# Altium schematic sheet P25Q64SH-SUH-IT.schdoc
size 127 x 101 mm
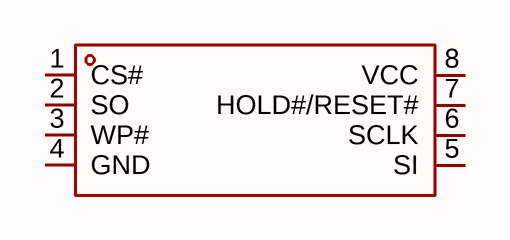
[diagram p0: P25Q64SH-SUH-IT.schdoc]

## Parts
U?  p25q64sh-suh-it  [SOIC-8_L5.3-W5.3-P1.27-LS8.0-BL]  (value not drawn)

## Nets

Not connected (* = marked no-connect by the designer): U? 1(CS#) 2(SO) 3(WP#) 4(GND) 5(SI) 6(SCLK) 7(HOLD#/RESET#) 8(VCC)

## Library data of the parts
U? = p25q64sh-suh-it: 接口类型:SPI;存储容量:64Mbit;时钟频率(fc):120MHz;; Manufacturer: PUYA(普冉); AddInBom: yes; ModelId: f83d990ad74f400caf5ac920b7771508; ModelName: SOIC-8_L5.3-W5.3-H1.9-LS7.9-P1.27; ModelTransform: 208.661,311.25654,0,0,0,0,-0.0005,0.0005,0; Interface: SPI; Memory Size: 64Mbit; Clock Frequency: 120MHz; Voltage - Supply: 2.3V~3.6V; Standby Supply Current: 10uA; Program / Erase Cycles: 100000次; Page Programming Time (Tpp): 2ms; Block Erase Time(tBE): 25ms; Data Retention - TDR (Year): 20年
